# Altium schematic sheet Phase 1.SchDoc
size Tabloid; SheetNumber: 3; SheetTotal: 7
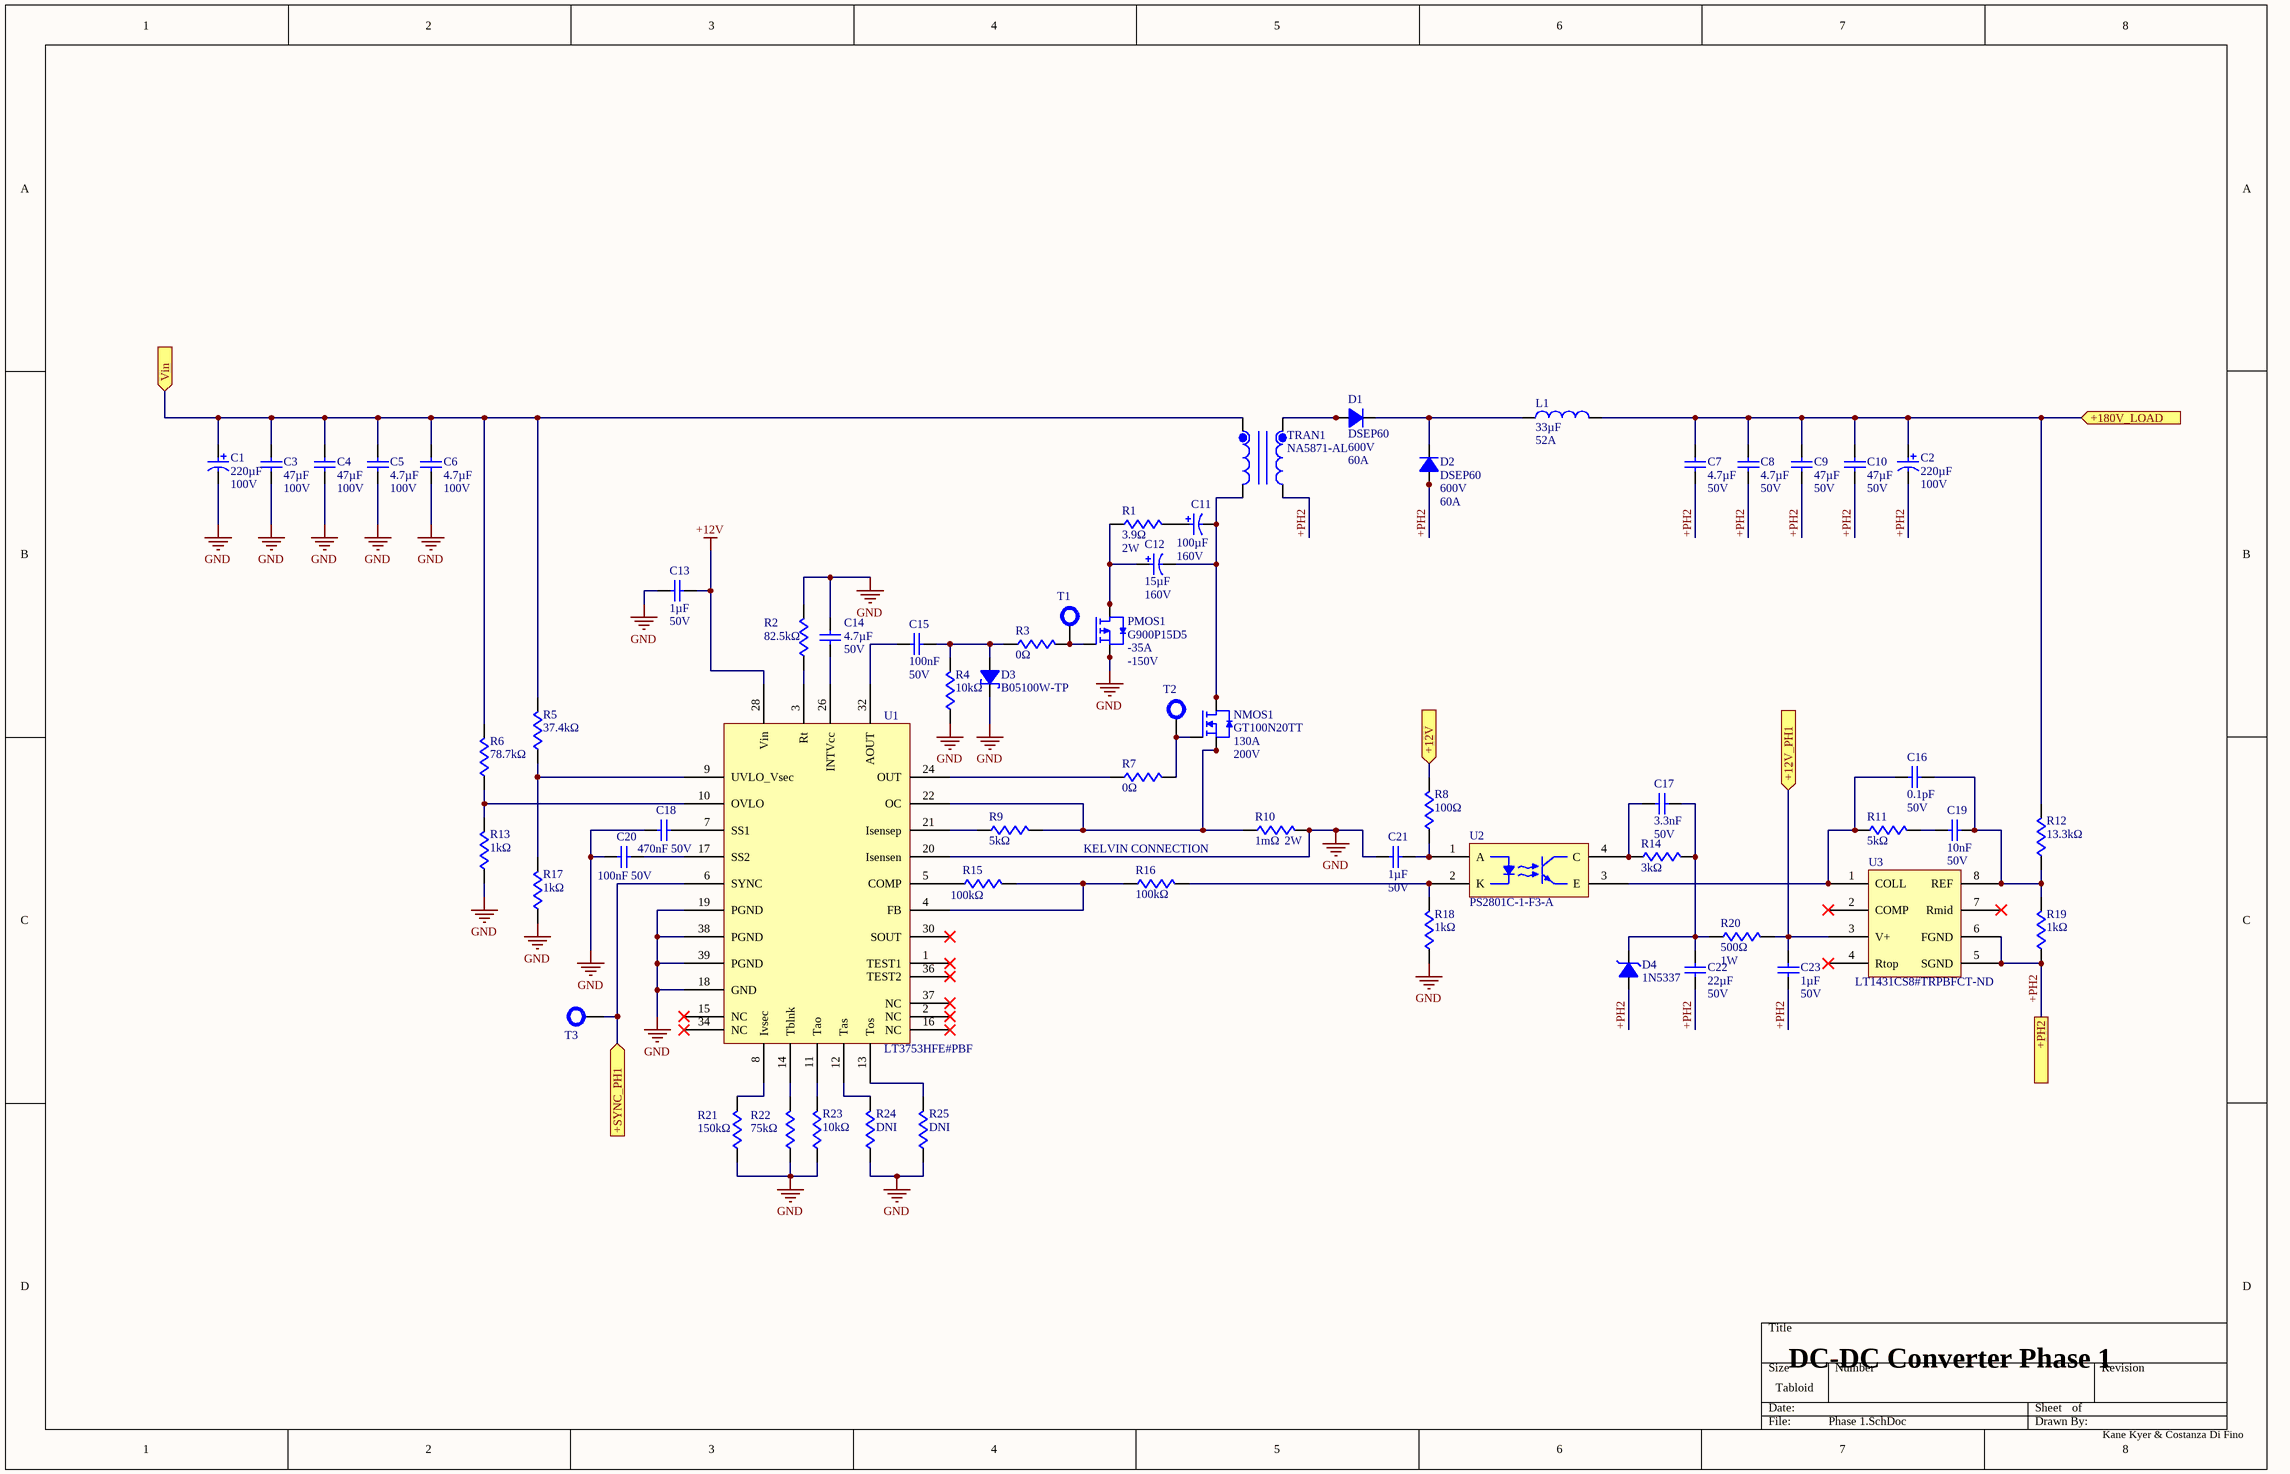
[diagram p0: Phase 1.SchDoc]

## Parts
C1  value 220µF  Voltage Rating: 100V  [C_AEC]  (hidden comment: AFK227M2AR44T-F)
C2  value 220µF  Voltage Rating: 100V  [C_AEC]  (hidden comment: AFK227M2AR44T-F)
C3  value 47µF  Voltage Rating: 100V  [C_CAA573]  (hidden comment: CAA573X7S2A476M640LH)
C4  value 47µF  Voltage Rating: 100V  [C_CAA573]  (hidden comment: CAA573X7S2A476M640LH)
C5  value 4.7µF  Voltage Rating (DC): 100V  [C_1210]  (hidden comment: GMC32X7S475K100NT)
C6  value 4.7µF  Voltage Rating (DC): 100V  [C_1210]  (hidden comment: GMC32X7S475K100NT)
C7  value 4.7µF  Voltage Rating (DC): 50V  [C_1206]  (hidden comment: GMC31X7R475K50NT)
C8  value 4.7µF  Voltage Rating (DC): 50V  [C_1206]  (hidden comment: GMC31X7R475K50NT)
C9  value 47µF  Voltage Rating (DC): 50V  [C_CKG57N]  (hidden comment: CKG57NX7R1H476M500JJ)
C10  value 47µF  Voltage Rating (DC): 50V  [C_CKG57N]  (hidden comment: CKG57NX7R1H476M500JJ)
C11  value 100µF  Voltage Rating (DC): 160V  [UUJ2C101MNJ1MS]  (hidden comment: UUJ2C101MNJ1MS)
C12  value 15µF  Voltage: 160V  [ULT2C150MNL1GS]  (hidden comment: ULT2C150MNL1GS)
C13  value 1µF  Voltage: 50V  [C_0805]  (hidden comment: CL21B105KBFNNNE)
C14  value 4.7µF  Voltage Rating (DC): 50V  [C_1206]  (hidden comment: GMC31X7R475K50NT)
C15  value 100nF  Voltage Rating: 50V  [C_0603]  (hidden comment: C0603C104K5RACTU)
C16  value 0.1pF  Voltage Rating: 50V  [C_0402]  (hidden comment: GJM1555C1HR10WB01D)
C17  value 3.3nF  Voltage Rating: 50V  [C_0603]  (hidden comment: GCM1885C1H332FA16D)
C18  value 470nF  Voltage Rating: 50V  [C_0402]  (hidden comment: GRM155R61H474KE11D)
C19  value 10nF  Voltage Rating: 50V  [C_0603]  (hidden comment: C0603C103K5RACTU)
C20  value 100nF  Voltage Rating: 50V  [C_0603]  (hidden comment: C0603C104K5RACTU)
C21  value 1µF  Voltage: 50V  [C_0805]  (hidden comment: CL21B105KBFNNNE)
C22  value 22µF  Voltage Rating (DC): 50V  [C_2220]  (hidden comment: GMC55X7R226M50NT)
C23  value 1µF  Voltage: 50V  [C_0805]  (hidden comment: CL21B105KBFNNNE)
D1  DSEP60  Vr: 600V  Io: 60A  [D_DSEP60]
D2  DSEP60  Vr: 600V  Io: 60A  [D_DSEP60]
D3  B05100W-TP  [D_B05100W]
D4  Supplier Part Number: 1N5337  [D_1N5337]  (hidden comment: 1N5337BRLG)
L1  value 33µF  Irms: 52A  [CPEX4141L-330MC]  (hidden comment: CPEX4141L-330MC)
NMOS1  Id: 130A  Vds: 200V  [GT100N20TT]  (hidden comment: GT100N20TT)
PMOS1  Id: -35A  Vds: -150V  [G900P15]  (hidden comment: G900P15D5)
R1  value 3.9Ω  Power Rating: 2W  [R_SM2W]  (hidden comment: SMW23R9JT)
R2  value 82.5kΩ  [R_0805]  (hidden comment: RMCF0805FT82K5)
R3  value 0Ω  [R_0805]  (hidden comment: CRCW08050000Z0EA)
R4  value 10kΩ  [R_0402]  (hidden comment: RM04F1002CT)
R5  value 37.4kΩ  [R_0603]  (hidden comment: RC0603FR-0737K4L)
R6  value 78.7kΩ  [R_0603]  (hidden comment: RC0603FR-0778K7L)
R7  value 0Ω  [R_0805]  (hidden comment: CRCW08050000Z0EA)
R8  value 100Ω  [R_0603]  (hidden comment: RC0603FR-07100RL)
R9  value 5kΩ  [R_0402]  (hidden comment: PNM0402E5001BST1)
R10  value 1mΩ  Power Rating: 2W  [R_2512]  (hidden comment: CRE2512-FZ-R001E-2)
R11  value 5kΩ  [R_0402]  (hidden comment: PNM0402E5001BST1)
R12  value 13.3kΩ  [R_0603]  (hidden comment: RMCF0603FT13K3)
R13  value 1kΩ  [R_0402]  (hidden comment: RM04F1001CT)
R14  value 3kΩ  [C_0402]  (hidden comment: AC0402FR-073KL)
R15  value 100kΩ  [R_0402]  (hidden comment: RM04F1003CT)
R16  value 100kΩ  [R_0402]  (hidden comment: RM04F1003CT)
R17  value 1kΩ  [R_0402]  (hidden comment: RM04F1001CT)
R18  value 1kΩ  [R_0402]  (hidden comment: RM04F1001CT)
R19  value 1kΩ  [R_0402]  (hidden comment: RM04F1001CT)
R20  value 500Ω  Power Rating: 1W  [R_WSC2515]  (hidden comment: WSC2515500R0FEB)
R21  value 150kΩ  [R_0603]  (hidden comment: RC0603FR-07150KL)
R22  value 75kΩ  [R_0603]  (hidden comment: AC0603FR-0775KL)
R23  value 10kΩ  [R_0402]  (hidden comment: RM04F1002CT)
R24  value DNI  [R_0805]  (hidden comment: CRCW08050000Z0EA)
R25  value DNI  [R_0805]  (hidden comment: CRCW08050000Z0EA)
T1  TEST  [TEST_POINT]  (value not drawn)
T2  TEST  [TEST_POINT]  (value not drawn)
T3  TEST  [TEST_POINT]  (value not drawn)
TRAN1  NA5871-AL  [NA5871-AL]
U1  LT3753HFE#PBF  [LT3753]
U2  PS2801C-1-F3-A  [PS2801C]
U3  Supplier Part Number: LT1431CS8#TRPBFCT-ND  [LT1431]  (hidden comment: LT1431CS8#TRPBF)

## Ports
+12V (in, see SHEET_MAP[4B], Externals[2A], Phase 2[4C], Phase 3[4C], Phase 4[4C], Phase 5[4B]), +12V_PH1 (in, see SHEET_MAP[4B], Externals[5B]), +180V_LOAD (in, see SHEET_MAP[4B], Externals[3B]), +PH2 (see SHEET_MAP[4B], Externals[4B], Phase 2[6B]), +SYNC_PH1 (in, see SHEET_MAP[4B], Externals[3C]), Vin (in, see SHEET_MAP[4B], Externals[1A], Phase 2[1B], Phase 3[1B], Phase 4[1B], Phase 5[1B])

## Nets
+12V: C13.2 U1.28(Vin)
GND: C1.2 C3.1 C4.1 C5.1 C6.1 C13.1 C14.1 C18.1 C20.1 C21.1 D3.1 PMOS1.1(S) PMOS1.2(S) PMOS1.3(S) R2.2 R4.1 R10.2 R13.1 R17.1 R18.1 R21.1 R22.1 R23.1 R24.1 R25.1 U1.18(GND) U1.19(PGND) U1.20(Isensen) U1.38(PGND) U1.39(PGND)
+12V: R8.2 ; port +12V  [a separate net that carries the same name]
+12V_PH1: C23.2 R20.2 U3.3(V+) ; port +12V_PH1
+180V_LOAD: C2.1 C7.2 C8.2 C9.2 C10.2 L1.2 R12.2 ; port +180V_LOAD
+PH2: C2.2 C7.1 C8.1 C9.1 C10.1 C22.1 C23.1 D2.1(A) D2.3(A) D4.2 R19.1 TRAN1.11 U3.5(SGND) U3.6(FGND) ; port +PH2
+SYNC_PH1: T3.1 U1.6(SYNC) ; port +SYNC_PH1
Vin: C1.1 C3.2 C4.2 C5.2 C6.2 R5.2 R6.2 TRAN1.1 ; port Vin
NetC11_1: C11.1 R1.2
NetC11_2: C11.2 C12.2 NMOS1.9(D) NMOS1.10(D) NMOS1.11(D) NMOS1.12(D) NMOS1.13(D) NMOS1.14(D) NMOS1.15(D) NMOS1.16(D) TRAN1.4
NetC12_1: C12.1 PMOS1.5(D) PMOS1.6(D) PMOS1.7(D) PMOS1.8(D) R1.1
NetC14_2: C14.2 U1.26(INTVcc)
NetC15_1: C15.1 U1.32(AOUT)
NetC15_2: C15.2 D3.2 R3.1 R4.2
NetC16_1: C16.1 R11.1 U2.3(E) U3.1(COLL)
NetC16_2: C16.2 C19.2 R12.1 R19.2 U3.8(REF)
NetC17_1: C17.1 R14.1 U2.4(C)
NetC17_2: C17.2 C22.2 D4.1 R14.2 R20.1
NetC18_2: C18.2 U1.7(SS1)
NetC19_1: C19.1 R11.2
NetC20_2: C20.2 U1.17(SS2)
NetC21_2: C21.2 R8.1 U2.1(A)
NetD1_1: D1.1(A) D1.3(A) TRAN1.6
NetD1_4: D1.4(C) D2.4(C) L1.1
NetNMOS1_1: NMOS1.1(S) NMOS1.2(S) NMOS1.3(S) NMOS1.4(S) NMOS1.5(S) NMOS1.6(S) NMOS1.7(S) R9.2 R10.1 U1.22(OC)
NetNMOS1_8: NMOS1.8(G) R7.2 T2.1
NetPMOS1_4: PMOS1.4(G) R3.2 T1.1
NetR2_1: R2.1 U1.3(Rt)
NetR5_1: R5.1 R17.2 U1.9(UVLO_Vsec)
NetR6_1: R6.1 R13.2 U1.10(OVLO)
NetR7_1: R7.1 U1.24(OUT)
NetR9_1: R9.1 U1.21(Isensep)
NetR15_1: R15.1 U1.5(COMP)
NetR15_2: R15.2 R16.1 U1.4(FB)
NetR16_2: R16.2 R18.2 U2.2(K)
NetR21_2: R21.2 U1.8(Ivsec)
NetR22_2: R22.2 U1.14(Tblnk)
NetR23_2: R23.2 U1.11(Tao)
NetR24_2: R24.2 U1.12(Tas)
NetR25_2: R25.2 U1.13(Tos)

Not connected (* = marked no-connect by the designer): U1 1(TEST1)* 2(NC)* 15(NC)* 16(NC)* 30(SOUT)* 34(NC)* 36(TEST2)* 37(NC)*; U3 2(COMP)* 4(Rtop)* 7(Rmid)*

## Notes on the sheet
- (near R16) KELVIN CONNECTION
- DC-DC Converter Phase 1
- Kane Kyer & Costanza Di Fino

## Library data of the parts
C1 C2 = AFK227M2AR44T-F: Radial Can - SMD ALUMINUM ELECTROLYTIC CAPACITOR AFK 100V 220muF ±20% 0.709Dia 18.00mm; Manufacturer: Cornell Dubilier; Dissipation Factor: 0.07%; ESR (Equivalent Series Resistance): 150mΩ; Leakage Current: 220µA; Life (Hours): 5000hours; Ripple Current: 687.75mA; Ripple Current (AC): 917mA
C3 C4 = CAA573X7S2A476M640LH: Multilayer Ceramic Chip Capacitors, Capacitance=47μF, LxWxT: 6.0x7.5x6.4mm; Manufacturer: TDK; Manufacturer Lifecycle Status: PRODUCTION; Tolerance: 20%
C5 C6 = GMC32X7S475K100NT: Ceramic Capacitor, Multilayer, Ceramic, 100V, 10% +Tol, 10% -Tol, X7S, 22% TC, 4.7uF, Surface Mount, 1210; Manufacturer: Cal-Chip Electronics
C7 C8 C14 = GMC31X7R475K50NT: Ceramic Capacitor, Multilayer, Ceramic, 50V, 10% +Tol, 10% -Tol, X7R, 15% TC, 4.7uF, Surface Mount, 1206; Manufacturer: Cal-Chip Electronics
C9 C10 = CKG57NX7R1H476M500JJ: Ceramic Capacitor, Multilayer, Ceramic, 50V, 20% +Tol, 20% -Tol, X7R, 15% TC, 47uF, Surface Mount, 2420; Manufacturer: TDK; Manufacturer Lifecycle Status: PRODUCTION
C11 = UUJ2C101MNJ1MS: Aluminum Electrolytic Capacitors 100 F 160 V Radial, SMD 5000 Hrs 105C; Manufacturer: Nichicon; Leakage Current: 740µA; Ripple Current: 380mA
C12 = ULT2C150MNL1GS: Radial Can - SMD ALUMINUM ELECTROLYTIC CAPACITOR ULT 160V 15muF ±20% 0.315Dia 8.00mm; Manufacturer: Nichicon; Leakage Current: 196µA; Life (Hours): 2000hours; Polarity: Polar; Ripple Current: 45mA
C13 C21 C23 = CL21B105KBFNNNE: 50V 1uF X7R ±10% 0805 Multilayer Ceramic Capacitors MLCC - SMD/SMT ROHS; Manufacturer: Samsung Electro-Mechanics
C15 C20 = C0603C104K5RACTU: 50V 100nF X7R ±10% 0603 Multilayer Ceramic Capacitors MLCC - SMD/SMT ROHS; Manufacturer: KEMET; Dissipation Factor: 2.5%; Temperature Coefficient: 30ppm/°C
C16 = GJM1555C1HR10WB01D: Multilayer Ceramic Capacitor, 0.1 pF, 50 V, ± 0.05pF, C0G (NP0), 0402 [1005 Metric]; Manufacturer: Murata; Manufacturer Lifecycle Status: IN PRODUCTION; Temperature Coefficient: 30ppm/°C
C17 = GCM1885C1H332FA16D: 50V 3.3nF C0G ±1% 0603 Multilayer Ceramic Capacitors MLCC - SMD/SMT ROHS; Manufacturer: Murata; Manufacturer Lifecycle Status: IN PRODUCTION; Temperature Coefficient: 30ppm/°C
C18 = GRM155R61H474KE11D: 50V 470nF X5R ±10% 0402 Multilayer Ceramic Capacitors MLCC - SMD/SMT ROHS; Manufacturer: Murata; Manufacturer Lifecycle Status: IN PRODUCTION
C19 = C0603C103K5RACTU: Capacitor, Multilayer, Ceramic, 50V, 10%, X7R, 15% Tc, 0.01Uf, Surface Mount, 0603; Manufacturer: KEMET; Dissipation Factor: 2.5%; Temperature Coefficient: 30ppm/°C
C22 = GMC55X7R226M50NT: Ceramic Capacitor, Multilayer, Ceramic, 50V, 20% +Tol, 20% -Tol, X7R, 15% TC, 22uF, Surface Mount, 2220; Manufacturer: Cal-Chip Electronics
D1 D2 = DSEP60-06AZ-TRL: Power Diode Discretes-FRED TO-; Manufacturer: IXYS
D3 = B05100W-TP: Rectifier Diode, Schottky, 1 Phase, 1 Element, 0.5A, 100V V(RRM), Silicon; Manufacturer: MCC; Forward Voltage: 850mV; Max Forward Surge Current (Ifsm): 5.5A; Max Output current: 500mA; Number of Elements: 1; Peak Reverse Current: 1µA
D4 = 1N5337BRLG: Zener Diode Single 4.7V 5% 2Ohm 5000mW 2-Pin Case 017AA-01 T/R / DIODE ZENER 4.7V 5W AXIAL; Manufacturer: onsemi; Manufacturer Lifecycle Status: ACTIVE; Forward Voltage: 1.2V; Impedance: 2Ω; Max Reverse Leakage Current: 5µA; Number of Elements: 1; Polarity: Unidirectional; Test Current: 260mA
L1 = CPEX4141L-330MC: Fixed Ind 33UH 52A 1.88 Mohm Th; Manufacturer: Codaca
NMOS1 = GT100N20TT: Mosfet N-ch 200V 130A 280W Tolt; Manufacturer: GoFord
PMOS1 = G900P15D5: P-150V, -60A, RD(max) Less Than 80mOhm at -10V, VTH -1V to -4V, DFN5x6-8L; Manufacturer: GoFord; Manufacturer Lifecycle Status: ACTIVE
R1 = SMW23R9JT: SM Series 3.9 Ohm ±5 % 2 W ±200 ppm/°C Surface Mount Wirewound Resistor; Manufacturer: TE Connectivity; Manufacturer Lifecycle Status: ACTIVE; Insulation Resistance: 10GΩ; Number of Resistors: 1; Operating Supply Voltage: 300V; Tolerance: 5%
R2 = RMCF0805FT82K5: Res Thick Film 0805 82.5K Ohm 1% 1/8W ±100ppm/°C Molded SMD SMD Paper T/R; Manufacturer: Stackpole Electronics; Max Power Dissipation: 125mW; Voltage Rating: 150V
R3 R7 R24 R25 = CRCW08050000Z0EA: Zero Ohm Resistor, Jumper, 0805 [2012 Metric], Thick Film, 125 mW, 2.5 A, Surface Mount Device; Manufacturer: Vishay; Manufacturer Package Identifier: CRCW0805-e3; Power Dissipation: 125mW; Temperature Coefficient: 100ppm/°C; Tolerance: 1%; Voltage Rating: 150V
R4 R23 = RM04F1002CT: Fixed Resistor, Metal Glaze/thick Film, 0.0625W, 10000ohm, 50V, 1% +/-Tol, Surface Mount, 0402; Manufacturer: Cal-Chip Electronics; Power Dissipation: 62.5mW; Power Rating: 63mW; Temperature Coefficient: 100ppm/°C
R5 = RC0603FR-0737K4L: 100mW Thick Film Resistors 75V ±100ppm/℃ ±1% 37.4kΩ 0603 Chip Resistor - Surface Mount ROHS; Manufacturer: Yageo Group; Temperature Coefficient: 100ppm/°C; Voltage Rating (DC): 50V
R6 = RC0603FR-0778K7L: Res Thick Film 0603 78.7K Ohm 1% 0.1W(1/10W) ±100ppm/C Pad SMD T/R; Manufacturer: Yageo Group; Power Dissipation: 100mW; Temperature Coefficient: 100ppm/°C; Voltage Rating: 75V; Voltage Rating (DC): 50V
R8 = RC0603FR-07100RL: Yageo RC0603FR-07100RL 0603 SMD Resistor 100 Ohm thin film chip resistor; Manufacturer: Yageo Group; Power Dissipation: 100mW; Temperature Coefficient: 100ppm/°C; Tolerance: 1%; Voltage Rating: 75V; Voltage Rating (DC): 50V
R9 R11 = PNM0402E5001BST1: Res Thin Film 0402 5K Ohm 0.1% 0.05W(1/20W) +/-25ppm/C Sulfur Resistant Pad SMD Medical T/R; Manufacturer: Vishay; Power Dissipation: 50mW; Temperature Coefficient: 25ppm/°C; Working Voltage: 75V
R10 = CRE2512-FZ-R001E-2: Res Thick Film 2512 1m Ohm 1% 2W ±75ppm/°C Molded SMD Embossed T/R; Manufacturer: Bourns; Temperature Coefficient: 50ppm/°C
R12 = RMCF0603FT13K3: Res Thick Film 0603 13.3K Ohm 1% 0.1W(1/10W) ±100ppm/C Pad SMD Automotive T/R; Manufacturer: Stackpole Electronics; Power Dissipation: 100mW; Temperature Coefficient: 100ppm/°C; Voltage Rating: 75V
R13 R17-R19 = RM04F1001CT: 62.5mW Thick Film Resistors ±100ppm/℃ ±1% 1kΩ 0402 Chip Resistor - Surface Mount ROHS; Manufacturer: Cal-Chip Electronics; Temperature Coefficient: 100ppm/°C; Working Voltage: 50V
R14 = AC0402FR-073KL: Res Thick Film 0402 3K Ohm 1% 0.063W(1/16W) ±100ppm/C Pad SMD Automotive T/R; Manufacturer: Yageo Group; Max Power Dissipation: 63mW; Power Dissipation: 62.5mW; Temperature Coefficient: 100ppm/°C; Voltage Rating: 50V
R15 R16 = RM04F1003CT: Fixed Resistor, Metal Glaze/thick Film, 0.0625W, 100000ohm, 50V, 1% +/-Tol, Surface Mount, 0402; Manufacturer: Cal-Chip Electronics; Power Dissipation: 62.5mW; Temperature Coefficient: 100ppm/°C
R20 = WSC2515500R0FEB: Fixed Resistor, Wire Wound, 1W, 500ohm, 22.3607V, 1% +/-Tol, 20ppm/Cel, Surface Mount, 2515; Manufacturer: Vishay; Temperature Coefficient: 20ppm/°C
R21 = RC0603FR-07150KL: 100mW Thick Film Resistors 75V ±100ppm/℃ ±1% 150kΩ 0603 Chip Resistor - Surface Mount ROHS; Manufacturer: Yageo Group; Temperature Coefficient: 100ppm/°C; Voltage Rating (AC): 50V
R22 = AC0603FR-0775KL: Res Thick Film 0603 75K Ohm 1% 0.1W(1/10W) ±100ppm/C Pad SMD T/R Automotive AEC-Q200; Manufacturer: Yageo Group; Max Power Dissipation: 100mW; Temperature Coefficient: 100ppm/°C; Voltage Rating: 75V
TRAN1 = NA5871-AL: Transformer, planar, for TI UCC28950, SMT, RoHS; Manufacturer: Coilcraft; Max Supply Voltage: 60V; Min Input Voltage: 38V; Power Rating: 800W
U1 = LT3753HFE#PBF: 500kHz 8.5V~100V Buck-boost type 1 TSSOP-38-EP-4.4mm DC-DC Controllers ROHS; Manufacturer: Analog Devices; Manufacturer Lifecycle Status: PRODUCTION; Clock Sync: Yes; Max Supply Voltage: 100V; Min Supply Voltage: 8.5V; Nominal Supply Voltage: 12V; Number of Output Phases: 1; Topology: Forward Converter
U2 = PS2801C-1-F3-A: Optocoupler DC-IN 1-CH Transistor DC-OUT 4-Pin SSOP T/R; Manufacturer: Renesas; Manufacturer Lifecycle Status: ACTIVE; Collector Emitter Breakdown Voltage: 80V; Collector Emitter Saturation Voltage: 300mV; Current Transfer Ratio: 50%; Dark Current: 100nA; Forward Current: 30mA; Forward Voltage: 1.4V; Input Current: 5mA; Isolation Voltage: 2.5kV; Max Power Dissipation: 120mW; Number of Elements: 1; Reverse Breakdown Voltage: 6V; Target Application: PLC\, Hybrid IC\, Power supply\, OA\, Measuring instrument\, Modem\, Communication devices
U3 = LT1431CS8#TRPBF: V-Ref Adjustable 2.5V to 36V 100mA 8-Pin SOIC N T/R; Manufacturer: Analog Devices; Manufacturer Lifecycle Status: PRODUCTION; Cathode Current: 1mA; Reference Type: Shunt; Temperature Coefficient: 30ppm/°C; Tolerance: 0.4%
